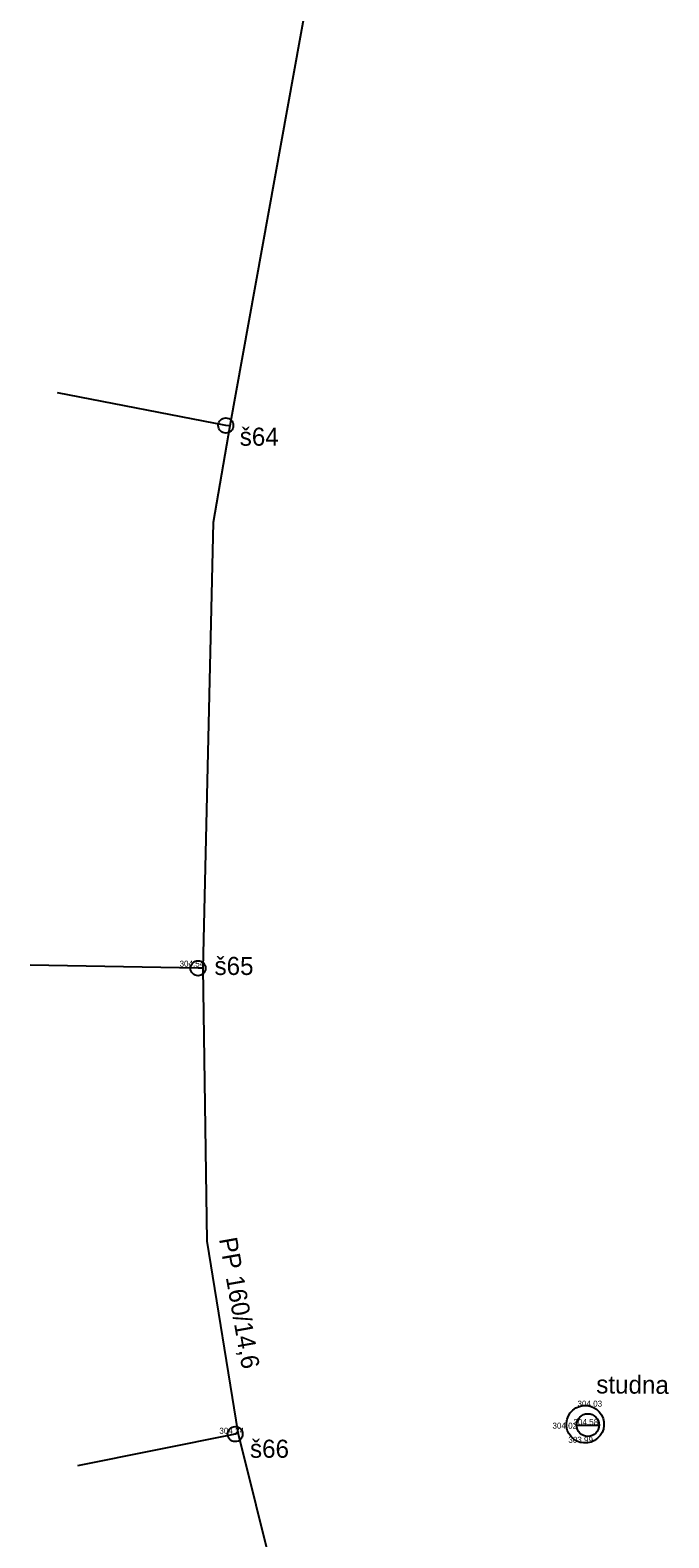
# Model space of a CAD drawing. Extents: x -734098 to -733915, y -1053674 to -1053435.
# Drawn here: x -734076.2 to -734055, y -1053555.4 to -1053505.4 of the extents above; entities that cross this region are included whole.
import ezdxf

# ---------------------------------------------------------------- set-up
doc = ezdxf.new("R2010")
doc.units = 0
for name, color, linetype in [('PIT_DIGI_vodovod', 7, 'Continuous'), ('PIT_ost_objekt', 7, 'Continuous'), ('PIT_ostatni_POPIS', 7, 'Continuous'), ('PIT_soupe', 7, 'Continuous'), ('PIT_vodovod', 7, 'Continuous'), ('PIT_vodovod_POPIS', 7, 'Continuous'), ('PIT_vysky', 7, 'Continuous')]:
    doc.layers.add(name, color=color, linetype=linetype)

msp = doc.modelspace()

# ---------------------------------------------------------------- linework, layer by layer
at = {"layer": 'PIT_DIGI_vodovod'}
for p, q in [((-734069.74, -1053518.49), (-734075.326, -1053517.408)), ((-734070.66, -1053536.5), (-734076.23, -1053536.401)), ((-734069.43, -1053551.96), (-734074.659, -1053553.009))]:
    msp.add_line(p, q, dxfattribs=at)
at = {"layer": 'PIT_ost_objekt'}
msp.add_line((-734058.104, -1053551.66), (-734057.354, -1053551.66), dxfattribs=at)
msp.add_circle((-734057.729, -1053551.66), 0.375, dxfattribs=at)
msp.add_ellipse((-734057.814, -1053551.632), major_axis=(0.542, 0.31), ratio=0.998987, dxfattribs=at)
at = {"layer": 'PIT_soupe'}
for centre in [(-734069.74, -1053518.49), (-734070.66, -1053536.5), (-734069.43, -1053551.96)]:
    msp.add_circle(centre, 0.25, dxfattribs=at)
at = {"layer": 'PIT_vodovod'}
for points in [[(-734065.97, -1053498.38), (-734065.99, -1053498.5), (-734069.61, -1053518.5)], [(-734069.61, -1053518.5), (-734070.16, -1053521.71), (-734070.5, -1053536.5)], [(-734069.61, -1053518.5), (-734069.74, -1053518.49)], [(-734070.5, -1053536.5), (-734070.66, -1053536.5)], [(-734070.5, -1053536.5), (-734070.37, -1053545.56), (-734069.34, -1053551.91)], [(-734069.34, -1053551.91), (-734069.43, -1053551.96)], [(-734069.34, -1053551.91), (-734064.6, -1053570.98), (-734063.23, -1053575.88)]]:
    msp.add_lwpolyline(points, dxfattribs=at)

# ---------------------------------------------------------------- texts
at = {"layer": 'PIT_ostatni_POPIS'}
for s, p in [('š64', (-734069.276, -1053519.161)), ('š65', (-734070.113, -1053536.724)), ('š66', (-734068.936, -1053552.745))]:
    msp.add_text(s, height=0.6, dxfattribs=at).set_placement(p)
msp.add_text('studna', height=0.6, rotation=359.5744, dxfattribs=at).set_placement((-734057.449, -1053550.609))
at = {"layer": 'PIT_vodovod_POPIS'}
msp.add_text('PP 160/14,6', height=0.6, rotation=280.0453, dxfattribs=at).set_placement((-734069.966, -1053545.484))
at = {"layer": 'PIT_vysky'}
for s, p in [('304.54', (-734071.273, -1053536.45)), ('304.03', (-734058.071, -1053551.05)), ('304.58', (-734058.203, -1053551.66)), ('304.24', (-734069.953, -1053551.95)), ('304.02', (-734058.901, -1053551.78)), ('303.99', (-734058.374, -1053552.25))]:
    msp.add_text(s, height=0.2, dxfattribs=at).set_placement(p)

doc.saveas('drawing.dxf')
